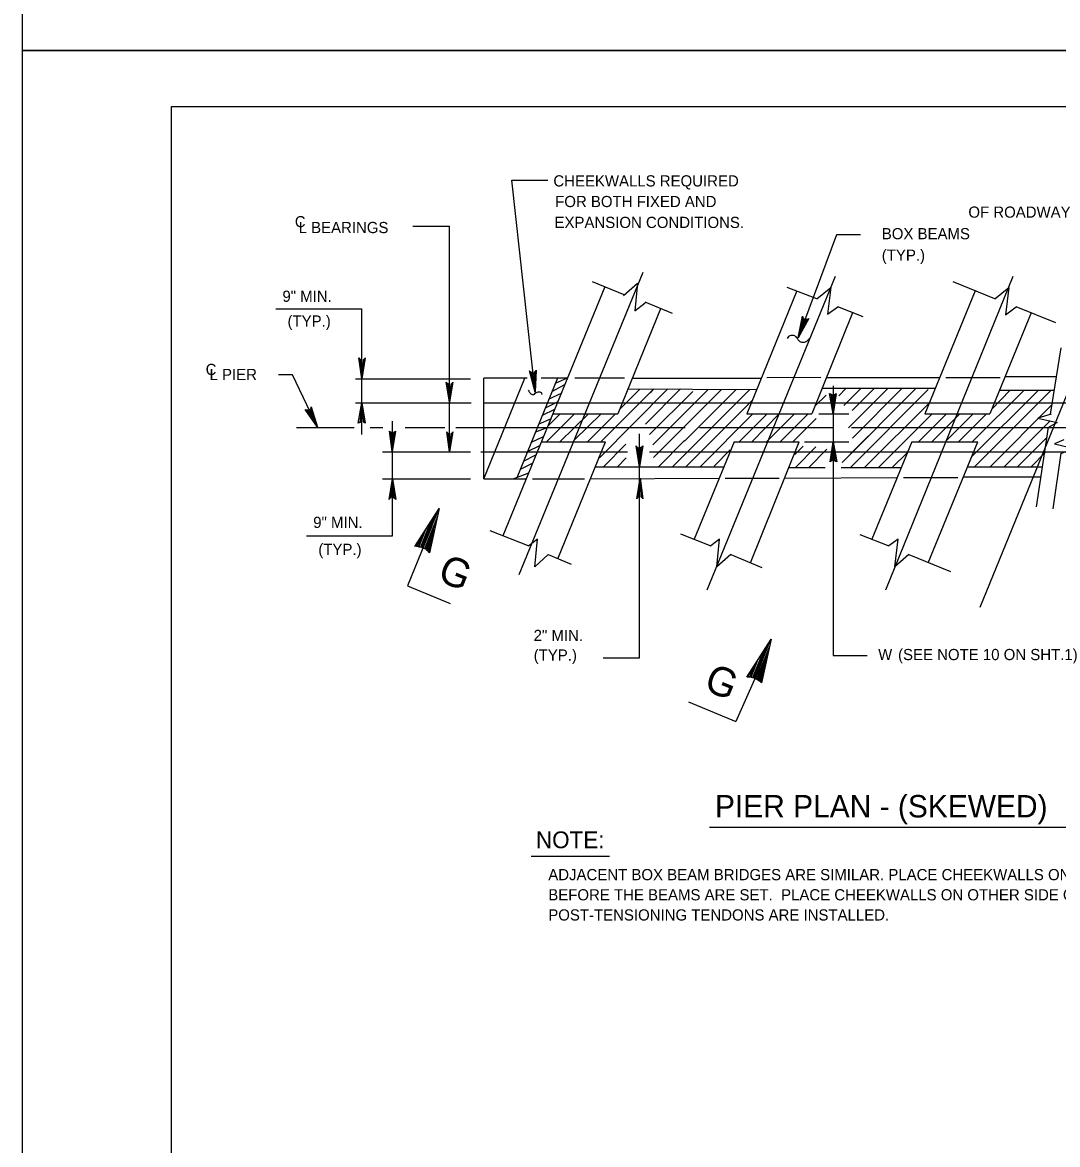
# Model space of a CAD drawing. Extents: x 641517 to 642372, y 298537 to 300319.
# Drawn here: x 641517 to 641794.6, y 298837.4 to 299138.1 of the extents above; entities that cross this region are included whole.
import ezdxf

# ---------------------------------------------------------------- set-up
doc = ezdxf.new("R2010")
doc.units = 0
doc.layers.add('2', color=7, linetype='Continuous')
doc.layers.add('PLT-BNDY', color=7, linetype='Continuous')

msp = doc.modelspace()

# ---------------------------------------------------------------- linework, layer by layer
at = {"layer": '2'}
for p, q in [((641557.05, 298551.62), (641557.05, 299115.62)), ((641557.05, 299115.62), (642343.05, 299115.62)), ((641654.52, 299039.02), (641648.25, 299095.82)), ((641648.25, 299095.82), (641657.93, 299095.82)), ((641773.78, 298981.44), (641819.22, 299092.64)), ((641621.68, 299083.5), (641631.58, 299083.5)), ((641631.58, 299036.52), (641631.58, 299083.5)), ((641735.26, 299081.16), (641725, 299053.62)), ((641741.71, 299081.16), (641735.26, 299081.16)), ((641683.42, 299071.08), (641650.12, 298990.08)), ((641734.9, 299070), (641700.52, 298985.94)), ((641782.6, 299070), (641748.4, 298985.94)), ((641673.16, 299067.3), (641645.8, 299000.52)), ((641678.38, 299065.14), (641669.92, 299068.56)), ((641724.64, 299066.22), (641711.22, 299033.25)), ((641730.04, 299064.06), (641722.12, 299067.12)), ((641772.52, 299066.22), (641758.98, 299033.25)), ((641777.74, 299064.06), (641766.58, 299068.56)), ((641691.34, 299060.1), (641683.96, 299063.16)), ((641584.99, 299061.36), (641608, 299061.36)), ((641608, 299041.92), (641608, 299061.36)), ((641688.1, 299061.36), (641676.64, 299033.25)), ((641739.58, 299060.28), (641728.66, 299033.25)), ((641742.46, 299059.2), (641735.62, 299061.9)), ((641787.46, 299060.28), (641776.43, 299033.25)), ((641794.12, 299057.58), (641783.5, 299061.9)), ((641792.68, 299033.1), (641795.56, 299050.92)), ((641589.46, 299043.72), (641585.68, 299043.72)), ((641596.12, 299029.68), (641589.46, 299043.72)), ((641606.38, 299042.64), (641637.16, 299042.64)), ((641608, 299036.16), (641608, 299042.64)), ((641640.76, 299015.82), (641640.76, 299042.82)), ((641640.76, 299015.82), (641651.74, 299042.82)), ((641652.38, 299042.82), (641640.76, 299042.82)), ((641660.51, 299042.82), (641649.64, 299016.09)), ((641663.08, 299042.82), (641656.1, 299042.82)), ((641663.08, 299042.82), (641659.91, 299041.36)), ((641678.46, 299042.82), (641665.15, 299042.82)), ((641680.54, 299042.82), (641715.1, 299042.82)), ((641731.13, 299042.99), (641716.58, 299042.84)), ((641732.56, 299043), (641762.98, 299043)), ((641764.64, 299043), (641779.18, 299043)), ((641794.3, 299043.18), (641780.44, 299043.18)), ((641662.36, 299041.02), (641659.05, 299039.24)), ((641671.72, 299021.4), (641690.08, 299039.94)), ((641672.11, 299025.76), (641685.58, 299039.22)), ((641677.12, 299034.36), (641682.52, 299039.76)), ((641679.46, 299039.94), (641713.84, 299039.76)), ((641684.07, 299030.43), (641693.5, 299039.94)), ((641685.17, 299027.65), (641696.74, 299039.22)), ((641685.4, 299038.86), (641686.3, 299039.94)), ((641686.05, 299024.94), (641700.88, 299039.76)), ((641689.18, 299024.46), (641704.48, 299039.76)), ((641691.34, 299019.06), (641712.04, 299039.76)), ((641694.58, 299025.9), (641708.44, 299039.76)), ((641731.48, 299040.12), (641761.9, 299040.12)), ((641734.41, 299040.74), (641734.41, 299033.25)), ((641735.91, 299038.07), (641737.82, 299039.98)), ((641736.78, 299020.22), (641756.68, 299040.12)), ((641737.28, 299035.48), (641741.92, 299040.12)), ((641738.51, 299029.51), (641749.12, 299040.12)), ((641739.04, 299018.88), (641759.92, 299039.76)), ((641739.52, 299034.12), (641745.52, 299040.12)), ((641739.58, 299026.68), (641752.9, 299040.12)), ((641771.62, 299021.76), (641789.44, 299039.58)), ((641771.68, 299025.76), (641785.66, 299039.58)), ((641774.5, 299021.22), (641792.86, 299039.58)), ((641776.84, 299034.36), (641781.88, 299039.58)), ((641779, 299039.58), (641793.76, 299039.58)), ((641606.38, 299036.16), (641637.34, 299036.16)), ((641608, 299027.7), (641608, 299036.16)), ((641631.58, 299023.02), (641631.58, 299036.16)), ((641640.61, 299036.16), (641973.04, 299036.16)), ((641660.38, 299036.34), (641657.23, 299034.77)), ((641661.46, 299038.68), (641658.21, 299037.19)), ((641694.94, 299019.06), (641712.58, 299036.7)), ((641729.5, 299035.26), (641732.51, 299038.27)), ((641742.82, 299018.88), (641760.1, 299035.98)), ((641659.66, 299034.36), (641656.41, 299032.74)), ((641657.53, 299025.76), (641665.03, 299033.25)), ((641661.25, 299033.25), (641657.86, 299029.86)), ((641659.21, 299033.25), (641676.64, 299033.25)), ((641661.13, 299025.76), (641668.82, 299033.25)), ((641665.09, 299026.28), (641672.23, 299033.25)), ((641668.51, 299025.76), (641676.01, 299033.25)), ((641698.72, 299019.06), (641712.91, 299033.25)), ((641709.19, 299025.76), (641716.69, 299033.25)), ((641711.22, 299033.25), (641728.66, 299033.25)), ((641712.62, 299025.76), (641719.92, 299033.25)), ((641716.57, 299025.76), (641724.07, 299033.25)), ((641720.17, 299025.76), (641727.67, 299033.25)), ((641730.55, 299033.25), (641738.6, 299033.25)), ((641734.41, 299033.25), (641734.41, 299025.76)), ((641750.56, 299022.84), (641760.97, 299033.25)), ((641757.25, 299025.76), (641764.75, 299033.25)), ((641758.98, 299033.25), (641776.43, 299033.25)), ((641760.85, 299025.76), (641768.35, 299033.25)), ((641764.77, 299026.07), (641771.95, 299033.25)), ((641768.05, 299025.76), (641775.55, 299033.25)), ((641776.48, 299019.06), (641793.04, 299035.62)), ((641616.28, 299023.02), (641616.28, 299031.3)), ((641658.76, 299031.84), (641655.47, 299030.43)), ((641723.59, 299025.76), (641729.84, 299032)), ((641780.26, 299019.06), (641792.5, 299031.3)), ((641606.03, 299029.5), (641590.54, 299029.5)), ((641613.7, 299029.5), (641610.31, 299029.5)), ((641630.32, 299029.5), (641619.68, 299029.5)), ((641694.76, 299029.5), (641633.2, 299029.5)), ((641653.53, 299025.66), (641656.78, 299027.16)), ((641657.68, 299029.5), (641654.61, 299028.32)), ((641682.52, 299019.06), (641682.52, 299027.88)), ((641734.37, 299029.5), (641698.54, 299029.5)), ((641739.18, 299022.63), (641743.9, 299027.34)), ((641992.66, 299029.5), (641739.33, 299029.5)), ((641772.34, 299019.06), (641782.6, 299029.32)), ((641783.86, 299019.06), (641791.78, 299026.98)), ((641788.9, 299008.26), (641792.14, 299029.68)), ((641655.7, 299024.64), (641652.52, 299023.17)), ((641656.2, 299025.76), (641673.38, 299025.76)), ((641660.56, 298994.4), (641673.38, 299025.76)), ((641672.8, 299019.06), (641678.78, 299025.1)), ((641686.27, 299021.55), (641690.44, 299025.72)), ((641687.56, 299019.06), (641694.58, 299026.08)), ((641707.84, 299025.76), (641697.1, 298999.62)), ((641707.84, 299025.76), (641725.31, 299025.76)), ((641712.22, 298993.32), (641725.31, 299025.76)), ((641724.1, 299022.3), (641726.33, 299024.53)), ((641724.28, 299018.88), (641729.79, 299024.39)), ((641726.69, 299025.76), (641738.6, 299025.76)), ((641727.88, 299018.88), (641732.74, 299023.75)), ((641734.41, 299025.76), (641734.41, 298968.48)), ((641755.54, 299025.76), (641744.8, 298999.62)), ((641755.54, 299025.76), (641773.17, 299025.76)), ((641759.92, 298993.32), (641773.17, 299025.76)), ((641613.58, 299023.02), (641637.16, 299023.02)), ((641616.28, 299015.82), (641616.28, 299022.84)), ((641639.96, 299023.02), (641679.28, 299023.02)), ((641654.62, 299022.12), (641651.44, 299020.54)), ((641676.58, 299019.06), (641678.9, 299021.39)), ((641682.52, 299014.02), (641682.52, 299023.38)), ((641685.2, 299023.02), (641974.66, 299023.02)), ((641702.5, 299019.24), (641706.82, 299023.56)), ((641746.6, 299018.88), (641751.28, 299023.56)), ((641750.2, 299018.88), (641754.34, 299022.84)), ((641774.5, 299021.22), (641776.84, 299023.56)), ((641787.46, 299019.06), (641791.24, 299022.84)), ((641793.4, 299007.72), (641795.56, 299022.66)), ((641653.9, 299019.96), (641650.53, 299018.28)), ((641670.64, 299019.06), (641705.02, 299019.06)), ((641722.48, 299018.88), (641732.23, 299018.88)), ((641736.51, 299018.88), (641752.72, 299018.88)), ((641770.36, 299019.06), (641790.52, 299019.06)), ((641613.58, 299015.82), (641637.16, 299015.82)), ((641616.28, 299000.52), (641616.28, 299015.82)), ((641640.76, 299015.82), (641652.1, 299015.82)), ((641648.61, 299015.82), (641652.82, 299017.44)), ((641653.76, 299015.82), (641667.75, 299015.82)), ((641669.38, 299015.82), (641703.76, 299016)), ((641705.42, 299016), (641719.96, 299016)), ((641721.38, 299016), (641751.64, 299016.18)), ((641753.3, 299016.18), (641767.84, 299016.18)), ((641769.28, 299016.36), (641790.16, 299016.36)), ((641682.52, 298967.87), (641682.52, 299014.02)), ((641626.79, 299003.1), (641620.31, 298987.12)), ((641593.25, 299000.52), (641616.28, 299000.52)), ((641642.38, 299001.96), (641652.82, 298997.82)), ((641693.5, 299001.06), (641701.6, 298997.82)), ((641741.56, 299000.88), (641749.3, 298997.82)), ((641658.04, 298995.48), (641664.16, 298992.96)), ((641707, 298995.48), (641715.28, 298992.06)), ((641754.7, 298995.48), (641765.86, 298990.98)), ((641620.31, 298987.12), (641631.74, 298982.39)), ((641672.71, 298967.87), (641682.52, 298967.87)), ((641734.41, 298968.48), (641743.54, 298968.48)), ((641714.75, 298965.27), (641708.27, 298950.8)), ((641695.66, 298955.99), (641708.27, 298950.8)), ((641701.22, 298922.48), (641818.84, 298922.48)), ((641653.47, 298914.67), (641674.47, 298914.67))]:
    msp.add_line(p, q, dxfattribs=at)
for points in [[(641678.2, 299064.96), (641681.98, 299068.2), (641681.26, 299060.82), (641683.96, 299062.98)], [(641730.04, 299064.06), (641733.82, 299067.12), (641732.92, 299059.92), (641735.62, 299061.9)], [(641777.74, 299064.06), (641781.52, 299067.12), (641780.62, 299059.74), (641783.5, 299061.9)], [(641727.58, 299058.57), (641727.14, 299058.52), (641725, 299053.62), (641727.58, 299058.57), (641727.91, 299058.75), (641725, 299053.62), (641726.61, 299058.71), (641726.31, 299059.03), (641725, 299053.62), (641726.17, 299059.4), (641726.31, 299059.03)], [(641608.72, 299047.86), (641608.36, 299047.68), (641608, 299042.64), (641608.72, 299047.86), (641608.9, 299048.22), (641608, 299042.64), (641607.82, 299047.68), (641607.46, 299047.86), (641608, 299042.64), (641607.28, 299048.22), (641607.46, 299047.86)], [(641654.61, 299044.6), (641654.23, 299044.35), (641654.52, 299039.02), (641654.61, 299044.6), (641654.82, 299044.91), (641654.52, 299039.02), (641653.68, 299044.29), (641653.26, 299044.44), (641654.52, 299039.02), (641652.97, 299044.71), (641653.26, 299044.44)], [(641632.3, 299041.38), (641631.94, 299041.2), (641631.58, 299036.34), (641632.3, 299041.38), (641632.48, 299041.74), (641631.58, 299036.34), (641631.4, 299041.2), (641631.04, 299041.38), (641631.58, 299036.34), (641630.68, 299041.74), (641631.04, 299041.38)], [(641607.46, 299030.94), (641607.82, 299031.12), (641608, 299036.16), (641607.46, 299030.94), (641607.1, 299030.76), (641608, 299036.16), (641608.36, 299031.12), (641608.72, 299030.94), (641608, 299036.16), (641608.9, 299030.76), (641608.72, 299030.94)], [(641735.04, 299038.48), (641734.69, 299038.3), (641734.41, 299033.25), (641735.04, 299038.48), (641735.22, 299038.66), (641734.41, 299033.25), (641734.15, 299038.29), (641733.78, 299038.46), (641734.41, 299033.25), (641733.42, 299038.63), (641733.78, 299038.46)], [(641594.5, 299034.72), (641594.14, 299034.36), (641596.12, 299029.68), (641594.5, 299034.72), (641594.5, 299035.08), (641596.12, 299029.68), (641593.6, 299034.18), (641593.24, 299034.18), (641596.12, 299029.68), (641592.88, 299034.36), (641593.24, 299034.18)], [(641792.86, 299033.1), (641789.26, 299032.02), (641794.48, 299030.94), (641791.96, 299029.5)], [(641616.93, 299028.36), (641616.57, 299028.18), (641616.21, 299023.14), (641616.93, 299028.36), (641617.11, 299028.54), (641616.21, 299023.14), (641616.03, 299028.18), (641615.67, 299028.36), (641616.21, 299023.14), (641615.49, 299028.54), (641615.67, 299028.36)], [(641632.3, 299028.06), (641631.94, 299027.88), (641631.58, 299023.02), (641632.3, 299028.06), (641632.48, 299028.42), (641631.58, 299023.02), (641631.4, 299027.88), (641631.04, 299028.06), (641631.58, 299023.02), (641630.86, 299028.42), (641631.04, 299028.06)], [(641683.06, 299024.28), (641682.7, 299024.1), (641682.52, 299019.06), (641683.06, 299024.28), (641683.42, 299024.64), (641682.52, 299019.06), (641682.16, 299024.1), (641681.8, 299024.28), (641682.52, 299019.06), (641681.62, 299024.64), (641681.8, 299024.28)], [(641733.77, 299020.53), (641734.12, 299020.71), (641734.41, 299025.76), (641733.77, 299020.53), (641733.59, 299020.34), (641734.41, 299025.76), (641734.66, 299020.72), (641735.03, 299020.55), (641734.41, 299025.76), (641735.39, 299020.37), (641735.03, 299020.55)], [(641796.28, 299026.26), (641793.76, 299025.18), (641798.98, 299023.92), (641795.38, 299022.48)], [(641615.56, 299010.6), (641615.92, 299010.78), (641616.28, 299015.82), (641615.56, 299010.6), (641615.38, 299010.24), (641616.28, 299015.82), (641616.46, 299010.78), (641616.82, 299010.6), (641616.28, 299015.82), (641617.18, 299010.24), (641616.82, 299010.6)], [(641681.98, 299010.78), (641682.34, 299010.96), (641682.7, 299016), (641681.98, 299010.78), (641681.8, 299010.42), (641682.7, 299016), (641682.88, 299010.96), (641683.24, 299010.78), (641682.7, 299016), (641683.42, 299010.42), (641683.24, 299010.78)], [(641622.25, 298997.7), (641628.73, 299007.85), (641626.14, 298995.97), (641625.92, 298996.19), (641626.36, 298997.49), (641626.79, 298999), (641625.71, 298996.41), (641625.49, 298996.62), (641627.22, 299000.73), (641627.44, 299002.24), (641625.28, 298996.84), (641625.06, 298997.05), (641627.87, 299003.97), (641628.3, 299005.69), (641624.84, 298997.05), (641624.41, 298997.27), (641628.52, 299007.21), (641628.73, 299007.85), (641627.87, 299006.56), (641624.2, 298997.27), (641623.98, 298997.49), (641627, 299005.05), (641626.36, 299003.97), (641623.76, 298997.49), (641623.33, 298997.49), (641625.28, 299002.45), (641624.41, 299000.94), (641623.12, 298997.7), (641622.68, 298997.7), (641623.76, 298999.65), (641622.68, 298998.35), (641622.47, 298997.7)], [(641658.04, 298995.48), (641654.44, 298992.24), (641655.16, 298999.62), (641652.82, 298997.82)], [(641707, 298995.48), (641703.22, 298992.24), (641703.94, 298999.62), (641701.6, 298997.82)], [(641754.7, 298995.48), (641750.92, 298992.24), (641751.82, 298999.62), (641749.3, 298997.82)], [(641711.3, 298962.67), (641717.78, 298972.83), (641715.18, 298961.16), (641714.97, 298961.38), (641715.4, 298962.46), (641715.83, 298963.97), (641714.75, 298961.59), (641714.54, 298961.59), (641716.26, 298965.91), (641716.48, 298967.43), (641714.32, 298961.81), (641714.1, 298962.03), (641716.91, 298968.94), (641717.34, 298970.88), (641713.89, 298962.24), (641713.46, 298962.24), (641717.56, 298972.39), (641717.78, 298972.83), (641716.91, 298971.53), (641713.24, 298962.46), (641713.02, 298962.46), (641716.05, 298970.23), (641715.4, 298968.94), (641712.81, 298962.46), (641712.38, 298962.67), (641714.32, 298967.43), (641713.46, 298965.91), (641712.16, 298962.67), (641711.94, 298962.67), (641712.81, 298964.83), (641711.73, 298963.32), (641711.51, 298962.67)]]:
    msp.add_lwpolyline(points, dxfattribs=at)
msp.add_arc((641711.38, 298957.21), 5.47, 45.6558, 89.9034, dxfattribs=at)
for points in [[(641728.05, 299053.4), (641727.51, 299052.86), (641726.25, 299052.32), (641725.35, 299052.68), (641724.81, 299053.4), (641724.09, 299054.12), (641722.83, 299054.12), (641722.47, 299053.94), (641722.11, 299053.4)], [(641652.64, 299039.55), (641652.94, 299039.1), (641653.54, 299038.51), (641654.29, 299038.51), (641654.74, 299038.96), (641655.34, 299039.1), (641656.09, 299038.96), (641656.24, 299038.66), (641656.39, 299038.36)]]:
    msp.add_spline(points, degree=3, dxfattribs=at)
at = {"layer": 'PLT-BNDY'}
for points in [[(641517.05, 299724.62), (642358.05, 299724.62), (642358.05, 299130.62), (641517.05, 299130.62)], [(641517.05, 299130.62), (642358.05, 299130.62), (642358.05, 298536.62), (641517.05, 298536.62)]]:
    msp.add_lwpolyline(points, close=True, dxfattribs=at)

# ---------------------------------------------------------------- texts
at = {"layer": '2'}
for s, height, p in [('CHEEKWALLS REQUIRED', 2.9998, (641659.39, 299094.16)), ('FOR BOTH FIXED AND', 2.9998, (641659.88, 299088.63)), ('  OF ROADWAY', 2.9998, (641768.43, 299085.79)), ('C', 2.97, (641590.09, 299083.25)), ('L BEARINGS ', 2.9998, (641591.1, 299081.66)), ('EXPANSION CONDITIONS. ', 2.9998, (641659.7, 299083.03)), ('BOX BEAMS', 3, (641747.45, 299080.01)), (' (TYP.)', 3, (641746.33, 299074.26)), ('9" MIN.', 3, (641586.75, 299063.24)), ('(TYP.)', 3, (641588.12, 299056.59)), ('C', 3, (641566.17, 299043.62)), ('L PIER ', 3, (641567.22, 299042.27)), ('9" MIN.', 3, (641595.01, 299002.63)), ('(TYP.)', 3, (641596.38, 298995.4)), ('2" MIN.', 3, (641654.1, 298972.33)), ('(TYP.)', 3, (641654.12, 298967.07)), ('W', 2.97, (641746.49, 298967.25)), ('(SEE NOTE 10 ON SHT.1)', 3, (641751.81, 298967.21)), ('PIER PLAN - (SKEWED) ', 6, (641702.72, 298925.05)), ('NOTE:', 4.5, (641654.72, 298916.8)), ('ADJACENT BOX BEAM BRIDGES ARE SIMILAR. PLACE CHEEKWALLS ON ONE SIDE OF BRIDGE', 3, (641658.03, 298908.22)), ('BEFORE THE BEAMS ARE SET.  PLACE CHEEKWALLS ON OTHER SIDE OF BRIDGE AFTER THE', 3, (641658.03, 298902.82)), ('POST-TENSIONING TENDONS ARE INSTALLED.', 3, (641658.03, 298897.42))]:
    msp.add_text(s, height=height, dxfattribs=at).set_placement(p)
for p in [(641627.99, 298988.64), (641699.39, 298959.34)]:
    msp.add_text('G', height=7.78, rotation=338, dxfattribs=at).set_placement(p)

doc.saveas('drawing.dxf')
